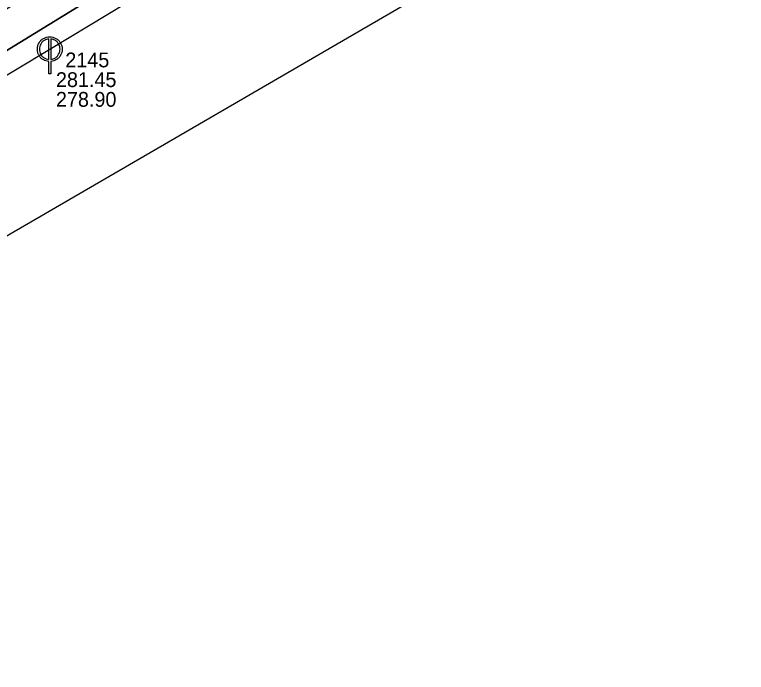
# Model space of a CAD drawing. Extents: x -571312 to -571060, y -1087128 to -1086933.
# Drawn here: x -571153.9 to -571079.7, y -1087127.5 to -1087060.8 of the extents above; entities that cross this region are included whole.
import ezdxf

# ---------------------------------------------------------------- set-up
doc = ezdxf.new("R2010")
doc.units = 0
for name, color, linetype in [('Default', 7, 'Continuous'), ('Kanalizační stoka', 7, 'Continuous'), ('Kanalizační šachta', 7, 'Continuous'), ('Parcela-polygon', 7, 'Continuous'), ('Popis šachty', 7, 'Continuous')]:
    doc.layers.add(name, color=color, linetype=linetype)

msp = doc.modelspace()

# ---------------------------------------------------------------- linework, layer by layer
at = {"layer": 'Default'}
for points in [[(-571150.483, -1087065.558), (-571150.741, -1087065.54), (-571151.003, -1087065.394), (-571151.3, -1087065.23), (-571151.465, -1087064.933), (-571151.63, -1087064.635), (-571151.63, -1087064.31), (-571151.63, -1087063.983), (-571151.462, -1087063.683), (-571151.293, -1087063.382), (-571150.995, -1087063.221), (-571150.697, -1087063.06), (-571150.38, -1087063.06), (-571150.065, -1087063.06), (-571149.766, -1087063.221), (-571149.467, -1087063.382), (-571149.298, -1087063.683), (-571149.13, -1087063.983), (-571149.13, -1087064.31), (-571149.13, -1087064.635), (-571149.295, -1087064.933), (-571149.46, -1087065.23), (-571149.757, -1087065.394), (-571150.019, -1087065.54), (-571150.277, -1087065.558)], [(-571150.483, -1087063.272), (-571150.68, -1087063.289), (-571150.895, -1087063.404), (-571151.144, -1087063.539), (-571151.283, -1087063.789), (-571151.422, -1087064.039), (-571151.422, -1087064.31), (-571151.422, -1087064.581), (-571151.286, -1087064.828), (-571151.149, -1087065.074), (-571150.9, -1087065.211), (-571150.688, -1087065.331), (-571150.483, -1087065.345)], [(-571150.277, -1087065.345), (-571150.072, -1087065.331), (-571149.858, -1087065.211), (-571149.611, -1087065.074), (-571149.474, -1087064.828), (-571149.338, -1087064.581), (-571149.338, -1087064.31), (-571149.338, -1087064.039), (-571149.478, -1087063.789), (-571149.618, -1087063.539), (-571149.867, -1087063.404), (-571150.08, -1087063.289), (-571150.277, -1087063.272)]]:
    msp.add_open_spline(points, degree=3, dxfattribs=at)
at = {"layer": 'Kanalizační stoka'}
for points in [[(-571150.38, -1087064.31), (-571136.8, -1087056.085), (-571123.22, -1087047.86)], [(-571170.61, -1087076.5), (-571160.495, -1087070.405), (-571150.38, -1087064.31)]]:
    msp.add_lwpolyline(points, dxfattribs=at)
at = {"layer": 'Kanalizační šachta'}
for points in [[(-571150.483, -1087065.345), (-571150.483, -1087063.272)], [(-571150.277, -1087063.272), (-571150.277, -1087065.345)], [(-571150.277, -1087065.558), (-571150.277, -1087066.81), (-571150.483, -1087066.81), (-571150.483, -1087065.558)]]:
    msp.add_lwpolyline(points, dxfattribs=at)
at = {"layer": 'Parcela-polygon'}
for points in [[(-571238.048, -1087115.573), (-571084.13, -1087021.07), (-571088.23, -1087015.62), (-571087.4, -1087014.88), (-571089.5, -1087012.31), (-571106.96, -1086996.89), (-571110.31, -1086993.17), (-571111.37, -1086999.41), (-571102.11, -1087007.86), (-571094.7, -1087015.4), (-571092.99, -1087017.97), (-571091.96, -1087020.97), (-571094.14, -1087023.09), (-571099.22, -1087026.2), (-571108.52, -1087031.9), (-571118.39, -1087037.91), (-571122.75, -1087040.66), (-571126.3, -1087042.9), (-571130.43, -1087045.33), (-571135.47, -1087048.29), (-571143.89, -1087053.63), (-571152.72, -1087058.97), (-571161.7, -1087064.52)], [(-571100.979, -1087051.983), (-571102.73, -1087043.67), (-571081.09, -1087028.01), (-571079.74, -1087027.03), (-571084.13, -1087021.07), (-571238.048, -1087115.573)], [(-571238.048, -1087115.573), (-571230.994, -1087127.523), (-571100.979, -1087051.983)]]:
    msp.add_lwpolyline(points, dxfattribs=at)

# ---------------------------------------------------------------- texts
at = {"layer": 'Popis šachty'}
for s, p in [('2145', (-571148.802, -1087066.151)), ('281.45', (-571149.751, -1087068.151)), ('278.90', (-571149.751, -1087070.151))]:
    msp.add_text(s, height=1.5, dxfattribs=at).set_placement(p)

doc.saveas('drawing.dxf')
